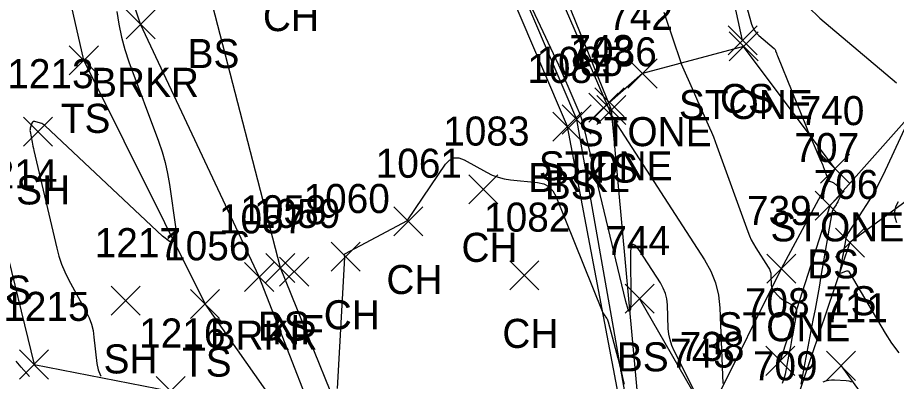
# Model space of a CAD drawing. Extents: x 1592612 to 1596497, y 111838 to 113741.
# Drawn here: x 1592810.3 to 1592870.8, y 113523.4 to 113548.4 of the extents above; entities that cross this region are included whole.
import ezdxf

# ---------------------------------------------------------------- set-up
doc = ezdxf.new("R2010")
doc.units = 0
for name, color, linetype in [('L_A', 7, 'Continuous'), ('L_I', 7, 'Continuous'), ('L_TIC', 7, 'Continuous'), ('LASF', 7, 'Continuous'), ('LAWE', 7, 'Continuous'), ('LELB', 7, 'Continuous'), ('LSOGCMA', 7, 'Continuous'), ('LSOGCMI', 7, 'Continuous')]:
    doc.layers.add(name, color=color, linetype=linetype)

msp = doc.modelspace()

# ---------------------------------------------------------------- linework, layer by layer
at = {"layer": 'L_TIC'}
for points in [[(1592817.761, 113546.936), (1592819.761, 113548.936)], [(1592819.761, 113546.936), (1592817.761, 113548.936)], [(1592859.223, 113545.827), (1592861.223, 113547.827)], [(1592861.223, 113545.827), (1592859.223, 113547.827)], [(1592859.296, 113545.413), (1592861.296, 113547.413)], [(1592861.296, 113545.413), (1592859.296, 113547.413)], [(1592859.296, 113545.413), (1592861.296, 113547.413)], [(1592861.296, 113545.413), (1592859.296, 113547.413)], [(1592813.853, 113544.459), (1592815.853, 113546.459)], [(1592815.853, 113544.459), (1592813.853, 113546.459)], [(1592852.331, 113543.545), (1592854.331, 113545.545)], [(1592854.331, 113543.545), (1592852.331, 113545.545)], [(1592852.331, 113543.545), (1592854.331, 113545.545)], [(1592854.331, 113543.545), (1592852.331, 113545.545)], [(1592850.058, 113541.555), (1592852.058, 113543.555)], [(1592852.058, 113541.555), (1592850.058, 113543.555)], [(1592849.644, 113541.193), (1592851.644, 113543.193)], [(1592851.644, 113541.193), (1592849.644, 113543.193)], [(1592850.192, 113541.037), (1592852.192, 113543.037)], [(1592852.192, 113541.037), (1592850.192, 113543.037)], [(1592847.805, 113540.382), (1592849.805, 113542.382)], [(1592849.805, 113540.382), (1592847.805, 113542.382)], [(1592847.162, 113539.894), (1592849.162, 113541.894)], [(1592849.162, 113539.894), (1592847.162, 113541.894)], [(1592810.704, 113539.535), (1592812.704, 113541.535)], [(1592812.704, 113539.535), (1592810.704, 113541.535)], [(1592865.6, 113536.992), (1592867.6, 113538.992)], [(1592867.6, 113536.992), (1592865.6, 113538.992)], [(1592865.6, 113536.992), (1592867.6, 113538.992)], [(1592867.6, 113536.992), (1592865.6, 113538.992)], [(1592841.375, 113535.584), (1592843.375, 113537.584)], [(1592843.375, 113535.584), (1592841.375, 113537.584)], [(1592865.23, 113534.449), (1592867.23, 113536.449)], [(1592867.23, 113534.449), (1592865.23, 113536.449)], [(1592836.203, 113533.371), (1592838.203, 113535.371)], [(1592838.203, 113533.371), (1592836.203, 113535.371)], [(1592866.616, 113531.911), (1592868.616, 113533.911)], [(1592868.616, 113531.911), (1592866.616, 113533.911)], [(1592831.887, 113530.945), (1592833.887, 113532.945)], [(1592833.887, 113530.945), (1592831.887, 113532.945)], [(1592827.396, 113530.17), (1592829.396, 113532.17)], [(1592829.396, 113530.17), (1592827.396, 113532.17)], [(1592828.34, 113529.918), (1592830.34, 113531.918)], [(1592830.34, 113529.918), (1592828.34, 113531.918)], [(1592861.894, 113530.12), (1592863.894, 113532.12)], [(1592863.894, 113530.12), (1592861.894, 113532.12)], [(1592861.894, 113530.12), (1592863.894, 113532.12)], [(1592863.894, 113530.12), (1592861.894, 113532.12)], [(1592825.928, 113529.545), (1592827.928, 113531.545)], [(1592827.928, 113529.545), (1592825.928, 113531.545)], [(1592844.19, 113529.664), (1592846.19, 113531.664)], [(1592846.19, 113529.664), (1592844.19, 113531.664)], [(1592816.724, 113527.908), (1592818.724, 113529.908)], [(1592818.724, 113527.908), (1592816.724, 113529.908)], [(1592822.204, 113527.691), (1592824.204, 113529.691)], [(1592824.204, 113527.691), (1592822.204, 113529.691)], [(1592852.127, 113528.052), (1592854.127, 113530.052)], [(1592854.127, 113528.052), (1592852.127, 113530.052)], [(1592810.425, 113523.523), (1592812.425, 113525.523)], [(1592812.425, 113523.523), (1592810.425, 113525.523)], [(1592861.822, 113523.774), (1592863.822, 113525.774)], [(1592863.822, 113523.774), (1592861.822, 113525.774)], [(1592866.005, 113523.43), (1592868.005, 113525.43)], [(1592868.005, 113523.43), (1592866.005, 113525.43)], [(1592819.841, 113521.69), (1592821.841, 113523.69)], [(1592821.841, 113521.69), (1592819.841, 113523.69)]]:
    msp.add_lwpolyline(points, dxfattribs=at)
at = {"layer": 'LASF'}
msp.add_lwpolyline([(1592858.251, 113521.771), (1592862.894, 113531.12), (1592866.6, 113537.992), (1592860.296, 113546.413), (1592853.331, 113544.545), (1592851.058, 113542.555)], dxfattribs=at)
at = {"layer": 'LAWE'}
for points in [[(1592886.537, 113460.922), (1592877.744, 113481.574), (1592863.095, 113501.144), (1592852.902, 113518.209), (1592848.805, 113541.382), (1592835.879, 113571.623), (1592826.212, 113589.998), (1592821.08, 113603.103), (1592811.502, 113625.047), (1592801.909, 113656.496), (1592787.746, 113677.481), (1592769.551, 113701.793), (1592752.509, 113717.946)], [(1592867.645, 113460.38), (1592859.409, 113477.515), (1592844.793, 113495.549), (1592832.37, 113516.6), (1592826.928, 113530.545), (1592818.762, 113547.936), (1592807.597, 113581.108), (1592797.669, 113603.177), (1592787.513, 113626.88), (1592776.477, 113646.362), (1592766.38, 113665.342), (1592748.736, 113682.085), (1592730.356, 113695.945)]]:
    msp.add_lwpolyline(points, dxfattribs=at)
at = {"layer": 'LELB'}
for points in [[(1592886.583, 113460.952), (1592879.778, 113482.315), (1592863.966, 113501.755), (1592853.366, 113518.29), (1592851.192, 113542.037), (1592841.019, 113567.093), (1592831.516, 113591.894), (1592821.816, 113602.808), (1592813.329, 113624.79), (1592804.232, 113657.067), (1592789.644, 113678.369), (1592770.935, 113703.549), (1592752.623, 113718.428)], [(1592886.43, 113460.851), (1592879.543, 113465.926), (1592876.137, 113481.194), (1592862.304, 113500.643), (1592852.529, 113517.932), (1592848.162, 113540.894), (1592835.177, 113571.255), (1592825.196, 113589.927), (1592820.421, 113603.303), (1592810.027, 113625.391), (1592799.468, 113655.332), (1592786.607, 113676.744), (1592768.899, 113700.806), (1592752.213, 113717.027)], [(1592869.098, 113460.398), (1592860.441, 113478.115), (1592844.631, 113496.556), (1592834.165, 113516.964), (1592828.396, 113531.171), (1592823.559, 113549.918), (1592808.456, 113581.723), (1592799.527, 113603.061), (1592789.48, 113627.849), (1592777.21, 113647.427), (1592766.461, 113666.146), (1592749.422, 113683.288), (1592730.933, 113697.021)], [(1592856.492, 113476.867), (1592843.193, 113495.045), (1592831.688, 113516.664), (1592823.204, 113528.692), (1592814.853, 113545.459), (1592806.797, 113580.845), (1592796.452, 113601.854), (1592785.293, 113626.354), (1592775.723, 113645.654), (1592766.309, 113664.453), (1592745.043, 113679.184), (1592727.847, 113694.217)], [(1592701.588, 113659.774), (1592726.097, 113635.895), (1592737.453, 113625.119), (1592757.272, 113620.552), (1592765.525, 113604.487), (1592785.217, 113593.362), (1592785.143, 113579.955), (1592783.097, 113567.939), (1592785.828, 113560.008), (1592797.4, 113544.62), (1592809.213, 113533.643), (1592811.425, 113524.524), (1592820.841, 113522.69), (1592826.429, 113512.914)], [(1592860.223, 113546.827), (1592857.498, 113559.424), (1592844.332, 113573.876), (1592833.529, 113599.277), (1592827.152, 113613.626), (1592814.151, 113635.371), (1592812.219, 113639.821)], [(1592884.313, 113549.407), (1592873.166, 113543.239), (1592866.23, 113535.449), (1592862.822, 113524.774)], [(1592885.411, 113547.376), (1592876.234, 113539.25), (1592867.617, 113532.911), (1592863.38, 113520.43), (1592865.405, 113513.944), (1592869.075, 113508.737), (1592880.629, 113500.08), (1592889.409, 113493.364), (1592892.469, 113484.552), (1592893.995, 113472.176), (1592892.484, 113467.779), (1592891.718, 113461.24)], [(1592853.127, 113529.053), (1592857.59, 113521.31), (1592858.606, 113515.284), (1592868.403, 113504.739), (1592877.011, 113497.321), (1592880.268, 113489.72), (1592885.949, 113485.322), (1592886.296, 113475.852), (1592890.02, 113471.216), (1592888.879, 113464.325)], [(1592867.005, 113524.43), (1592872.973, 113516.163), (1592876.794, 113505.866)]]:
    msp.add_lwpolyline(points, dxfattribs=at)
at = {"layer": 'LSOGCMA'}
for points in [[(1592843.782, 113558.82), (1592850.972, 113542.212), (1592851.015, 113542.106), (1592851.054, 113541.999), (1592851.088, 113541.89), (1592851.117, 113541.779), (1592851.255, 113541.203), (1592851.264, 113541.169), (1592851.271, 113541.158), (1592851.275, 113541.171), (1592851.276, 113541.206), (1592851.275, 113541.394), (1592851.278, 113541.43), (1592851.287, 113541.444), (1592851.303, 113541.437), (1592851.325, 113541.409), (1592857.61, 113531.714), (1592858.041, 113530.943), (1592858.36, 113530.136), (1592858.566, 113529.294), (1592858.659, 113528.415), (1592858.873, 113523.217)], [(1592811.1, 113523.697), (1592810.533, 113524.342), (1592810.2, 113524.762)]]:
    msp.add_lwpolyline(points, dxfattribs=at)
at = {"layer": 'LSOGCMI'}
for points in [[(1592857.654, 113559.389), (1592860.846, 113547.933), (1592860.926, 113547.708), (1592861.037, 113547.502), (1592861.178, 113547.316), (1592861.35, 113547.149), (1592862.397, 113546.265), (1592862.431, 113546.233), (1592862.459, 113546.197), (1592862.482, 113546.158), (1592862.499, 113546.115), (1592862.56, 113545.937), (1592862.575, 113545.892), (1592862.591, 113545.848), (1592862.608, 113545.804), (1592862.625, 113545.76), (1592864.6, 113540.888), (1592864.701, 113540.643), (1592864.803, 113540.399), (1592864.907, 113540.156), (1592865.012, 113539.913), (1592865.625, 113538.521), (1592865.639, 113538.49), (1592865.653, 113538.459), (1592865.667, 113538.428), (1592865.68, 113538.397), (1592865.736, 113538.273), (1592865.749, 113538.242), (1592865.762, 113538.211), (1592865.775, 113538.179), (1592865.786, 113538.147), (1592866.118, 113537.229), (1592866.135, 113537.193), (1592866.159, 113537.164), (1592866.189, 113537.142), (1592866.225, 113537.126), (1592866.384, 113537.075), (1592866.422, 113537.061), (1592866.458, 113537.043), (1592866.492, 113537.02), (1592866.524, 113536.994), (1592866.958, 113536.6), (1592867.024, 113536.522), (1592867.057, 113536.438), (1592867.059, 113536.347), (1592867.028, 113536.249), (1592866.813, 113535.787), (1592866.779, 113535.717), (1592866.743, 113535.648), (1592866.704, 113535.58), (1592866.663, 113535.514), (1592866.494, 113535.251), (1592866.456, 113535.183), (1592866.424, 113535.113), (1592866.4, 113535.041), (1592866.383, 113534.965), (1592865.622, 113530.59), (1592865.489, 113529.835), (1592865.353, 113529.081), (1592865.214, 113528.328), (1592865.072, 113527.575), (1592864.231, 113523.173)], [(1592857.469, 113521.578), (1592855.51, 113525.46), (1592855.347, 113525.83), (1592855.226, 113526.211), (1592855.146, 113526.602), (1592855.109, 113527.004), (1592855.042, 113528.635), (1592854.999, 113529.035), (1592854.906, 113529.418), (1592854.761, 113529.785), (1592854.564, 113530.136), (1592853.118, 113532.366), (1592852.843, 113532.719), (1592852.648, 113532.806), (1592852.532, 113532.626), (1592852.497, 113532.18), (1592852.52, 113528.888), (1592852.504, 113528.329), (1592852.442, 113528.136), (1592852.336, 113528.309), (1592852.185, 113528.847), (1592849.34, 113540.707), (1592849.239, 113541.09), (1592849.122, 113541.467), (1592848.989, 113541.839), (1592848.839, 113542.206), (1592848.209, 113543.662), (1592848.05, 113544.026), (1592847.889, 113544.388), (1592847.725, 113544.749), (1592847.559, 113545.109), (1592844.5, 113551.673)], [(1592864.736, 113549.133), (1592865.546, 113548.344), (1592870.817, 113543.899), (1592870.824, 113543.892)], [(1592817.121, 113548.815), (1592817.252, 113547.929), (1592817.435, 113547.054), (1592817.671, 113546.193), (1592817.959, 113545.344), (1592819.994, 113539.893), (1592820.244, 113539.162), (1592820.454, 113538.42), (1592820.624, 113537.669), (1592820.753, 113536.907), (1592821.187, 113533.839), (1592821.212, 113533.234), (1592821.068, 113532.953), (1592820.755, 113532.997), (1592820.274, 113533.364), (1592812.188, 113540.947), (1592812.116, 113541.007), (1592812.039, 113541.057), (1592811.957, 113541.097), (1592811.869, 113541.128), (1592811.475, 113541.241), (1592811.407, 113541.251), (1592811.351, 113541.237), (1592811.307, 113541.199), (1592811.276, 113541.138), (1592811.175, 113540.846), (1592811.155, 113540.773), (1592811.145, 113540.699), (1592811.144, 113540.624), (1592811.154, 113540.548), (1592811.289, 113539.83), (1592811.318, 113539.685), (1592811.347, 113539.54), (1592811.379, 113539.396), (1592811.412, 113539.252), (1592812.987, 113532.523), (1592813.137, 113531.967), (1592813.323, 113531.424), (1592813.545, 113530.895), (1592813.803, 113530.38), (1592815.02, 113528.141), (1592815.218, 113527.73), (1592815.373, 113527.305), (1592815.484, 113526.867), (1592815.552, 113526.415), (1592815.739, 113524.582), (1592815.828, 113524.151), (1592816.004, 113523.773), (1592816.055, 113523.71)], [(1592854.803, 113548.77), (1592854.97, 113548.292), (1592855.92, 113545.444), (1592855.926, 113545.425), (1592855.932, 113545.406), (1592855.938, 113545.387), (1592855.944, 113545.369), (1592855.968, 113545.293), (1592855.974, 113545.274), (1592855.981, 113545.256), (1592855.988, 113545.237), (1592855.996, 113545.219), (1592856.842, 113543.297), (1592856.98, 113542.986), (1592857.117, 113542.676), (1592857.255, 113542.365), (1592857.393, 113542.054), (1592857.947, 113540.812), (1592858.082, 113540.5), (1592858.212, 113540.186), (1592858.336, 113539.87), (1592858.454, 113539.552), (1592860.577, 113533.675), (1592860.692, 113533.382), (1592860.824, 113533.098), (1592860.971, 113532.821), (1592861.135, 113532.553), (1592861.998, 113531.221), (1592862.071, 113531.09), (1592862.125, 113530.953), (1592862.16, 113530.81), (1592862.176, 113530.661), (1592862.204, 113529.99), (1592862.218, 113529.873), (1592862.252, 113529.765), (1592862.305, 113529.665), (1592862.378, 113529.573), (1592862.706, 113529.221), (1592862.791, 113529.136), (1592862.882, 113529.059), (1592862.978, 113528.989), (1592863.08, 113528.926), (1592863.706, 113528.573), (1592863.825, 113528.485), (1592863.901, 113528.377), (1592863.937, 113528.249), (1592863.93, 113528.101), (1592863.676, 113526.64), (1592863.623, 113526.344), (1592863.57, 113526.048), (1592863.516, 113525.753), (1592863.46, 113525.457), (1592863.155, 113523.862), (1592863.074, 113523.531), (1592862.959, 113523.214)], [(1592871.812, 113541.682), (1592869.904, 113537.58), (1592869.689, 113537.138), (1592869.46, 113536.703), (1592869.216, 113536.277), (1592868.958, 113535.858), (1592867.537, 113533.64), (1592867.458, 113533.503), (1592867.394, 113533.36), (1592867.345, 113533.211), (1592867.31, 113533.057), (1592867.201, 113532.427), (1592867.173, 113532.27), (1592867.144, 113532.112), (1592867.115, 113531.955), (1592867.086, 113531.798), (1592866.919, 113530.925), (1592866.915, 113530.86), (1592866.934, 113530.823), (1592866.974, 113530.813), (1592867.037, 113530.83), (1592867.332, 113530.955), (1592867.402, 113530.974), (1592867.463, 113530.967), (1592867.517, 113530.936), (1592867.562, 113530.879), (1592870.04, 113526.686), (1592870.492, 113525.985), (1592870.996, 113525.327)], [(1592832.334, 113522.871), (1592832.819, 113531.889), (1592832.82, 113531.911), (1592832.819, 113531.933), (1592832.818, 113531.956), (1592832.816, 113531.978), (1592832.806, 113532.067), (1592832.806, 113532.088), (1592832.812, 113532.106), (1592832.823, 113532.121), (1592832.84, 113532.133), (1592837.137, 113534.436), (1592837.14, 113534.438), (1592837.143, 113534.44), (1592837.145, 113534.442), (1592837.147, 113534.445), (1592837.161, 113534.467), (1592837.163, 113534.47), (1592839.769, 113538.3), (1592840.035, 113538.593), (1592840.336, 113538.741), (1592840.671, 113538.745), (1592841.04, 113538.603), (1592842.587, 113537.746), (1592842.981, 113537.554), (1592843.387, 113537.403), (1592843.807, 113537.295), (1592844.24, 113537.23), (1592846.103, 113537.043), (1592846.524, 113536.95), (1592846.874, 113536.762), (1592847.153, 113536.478), (1592847.36, 113536.1), (1592850.549, 113528.195), (1592850.578, 113528.131), (1592850.61, 113528.068), (1592850.646, 113528.008), (1592850.686, 113527.95), (1592850.854, 113527.721), (1592850.893, 113527.662), (1592850.926, 113527.601), (1592850.953, 113527.537), (1592850.974, 113527.47), (1592851.634, 113524.952), (1592851.747, 113524.509), (1592851.856, 113524.065), (1592851.959, 113523.619), (1592852.057, 113523.173)], [(1592870.937, 113535.709), (1592870.768, 113535.369), (1592870.693, 113535.021), (1592870.711, 113534.666), (1592870.824, 113534.303)], [(1592865.784, 113523.333), (1592865.97, 113523.4), (1592866.16, 113523.445), (1592866.354, 113523.467), (1592866.552, 113523.466), (1592867.351, 113523.42), (1592867.544, 113523.394), (1592867.726, 113523.337)]]:
    msp.add_lwpolyline(points, dxfattribs=at)

# ---------------------------------------------------------------- texts
at = {"layer": 'L_A'}
for s, p in [('CH', (1592827.188, 113547.46)), ('BS', (1592822, 113544.918)), ('BRKR', (1592815.352, 113542.936)), ('STONE', (1592855.84, 113541.413)), ('CS', (1592858.664, 113541.827)), ('TS', (1592813.263, 113540.459)), ('STONE', (1592848.875, 113539.545)), ('STONE', (1592846.187, 113537.193)), ('TS', (1592849.601, 113537.037)), ('BRKL', (1592845.45, 113536.382)), ('SH', (1592810.192, 113535.535)), ('BS', (1592846.603, 113535.894)), ('STONE', (1592862.143, 113532.992)), ('CH', (1592840.863, 113531.584)), ('BS', (1592864.671, 113530.449)), ('CH', (1592835.691, 113529.371)), ('BS', (1592807.653, 113528.643)), ('TS', (1592866.026, 113527.911)), ('CH', (1592831.375, 113526.945)), ('BS', (1592826.837, 113526.17)), ('NF', (1592827.82, 113525.918)), ('CH', (1592843.678, 113525.664)), ('STONE', (1592858.438, 113526.12)), ('BRKR', (1592823.519, 113525.545)), ('SH', (1592816.212, 113523.908)), ('BS', (1592851.568, 113524.052)), ('TS', (1592821.614, 113523.691))]:
    msp.add_text(s, height=2, dxfattribs=at).set_placement(p)
at = {"layer": 'L_I'}
for s, p in [('742', (1592850.969, 113547.545)), ('743', (1592848.282, 113545.193)), ('1086', (1592848.365, 113545.037)), ('1084', (1592845.391, 113543.894)), ('1085', (1592846.033, 113544.382)), ('1213', (1592809.578, 113543.535)), ('740', (1592864.151, 113540.992)), ('1083', (1592839.603, 113539.584)), ('707', (1592863.789, 113538.449)), ('1061', (1592834.951, 113537.371)), ('1214', (1592807.087, 113536.643)), ('706', (1592865.12, 113535.911)), ('1060', (1592829.981, 113534.945)), ('1058', (1592825.624, 113534.17)), ('1057', (1592824.156, 113533.545)), ('1059', (1592826.56, 113533.918)), ('1082', (1592842.418, 113533.664)), ('739', (1592860.524, 113534.12)), ('1217', (1592815.598, 113531.908)), ('744', (1592850.765, 113532.052)), ('1056', (1592820.377, 113531.691)), ('1215', (1592809.299, 113527.523)), ('708', (1592860.381, 113527.774)), ('711', (1592865.776, 113527.43)), ('1216', (1592818.66, 113525.69)), ('738', (1592855.889, 113524.771)), ('745', (1592855.228, 113524.31)), ('709', (1592860.932, 113523.43))]:
    msp.add_text(s, height=2, dxfattribs=at).set_placement(p)

doc.saveas('drawing.dxf')
